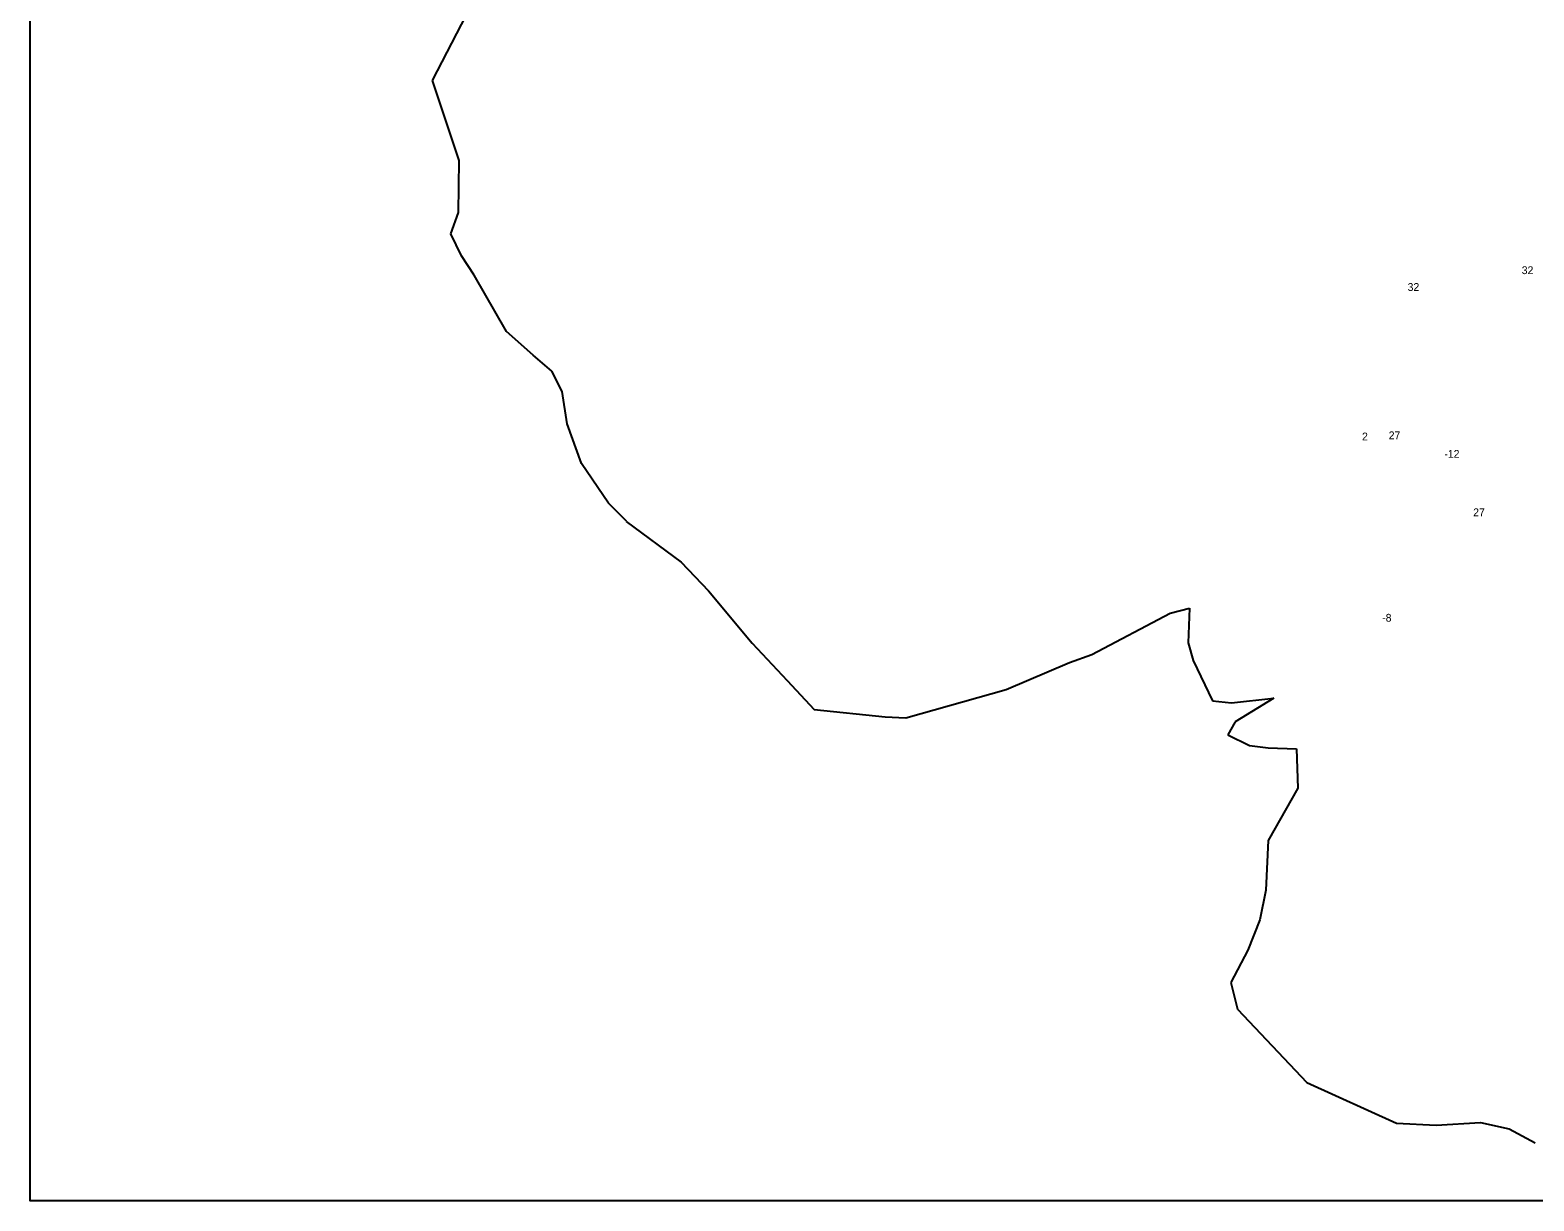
# Model space of a CAD drawing. Extents: x -772884 to -769704, y -986653 to -984166.
# Drawn here: x -772884 to -771287, y -986653 to -985410 of the extents above; entities that cross this region are included whole.
import ezdxf

# ---------------------------------------------------------------- set-up
doc = ezdxf.new("R2010")
doc.units = 0
doc.layers.add('Vrstva 15', color=7, linetype='Continuous')
doc.layers.add('Vrstva 24', color=7, linetype='Continuous')

msp = doc.modelspace()

# ---------------------------------------------------------------- linework, layer by layer
at = {"layer": 'Vrstva 15'}
for p, q in [((-772456.23, -985463.11), (-772400.73, -985355.31)), ((-772427.89, -985548.21), (-772456.23, -985463.11)), ((-772428.63, -985603.28), (-772427.89, -985548.21)), ((-772436.92, -985626), (-772428.63, -985603.28)), ((-772425.4, -985649.39), (-772436.92, -985626)), ((-772412.04, -985669.95), (-772425.4, -985649.39)), ((-772377.83, -985729.71), (-772412.04, -985669.95)), ((-772349.21, -985754.68), (-772377.83, -985729.71)), ((-772329.68, -985771.86), (-772349.21, -985754.68)), ((-772318.52, -985793.3), (-772329.68, -985771.86)), ((-772313.24, -985827.67), (-772318.52, -985793.3)), ((-772298.12, -985869.96), (-772313.24, -985827.67)), ((-772269.49, -985912.11), (-772298.12, -985869.96)), ((-772250.262, -985931.088), (-772269.49, -985912.11)), ((-772250.56, -985931.49), (-772192.24, -985974.75)), ((-772192.24, -985974.75), (-772163.18, -986005.14)), ((-772163.18, -986005.14), (-772116.66, -986060.78)), ((-771673.06, -986028.88), (-771652.46, -986023.5)), ((-771652.46, -986023.5), (-771653.63, -986060.2)), ((-771756.06, -986072.81), (-771673.06, -986028.88)), ((-772116.66, -986060.78), (-772079.67, -986100.27)), ((-771779.84, -986081.04), (-771756.06, -986072.81)), ((-771653.63, -986060.2), (-771648.5, -986079.14)), ((-771847.2, -986109.75), (-771779.84, -986081.04)), ((-771648.5, -986079.14), (-771627.8, -986121.91)), ((-772079.67, -986100.27), (-772050.91, -986131.15)), ((-771953.61, -986140.1), (-771847.2, -986109.75)), ((-771627.8, -986121.91), (-771607.7, -986123.97)), ((-771607.7, -986123.97), (-771562.93, -986119.01)), ((-771562.93, -986119.01), (-771603.88, -986144.12)), ((-772050.91, -986131.15), (-771975.4, -986138.86)), ((-771975.4, -986138.86), (-771953.61, -986140.1)), ((-771603.88, -986144.12), (-771611.51, -986157.92)), ((-771611.51, -986157.92), (-771588.62, -986169.52)), ((-771588.62, -986169.52), (-771568.8, -986171.72)), ((-771568.8, -986171.72), (-771538.71, -986173.04)), ((-771538.71, -986173.04), (-771537.4, -986214.71)), ((-771537.4, -986214.71), (-771569.02, -986270.36)), ((-771569.02, -986270.36), (-771571.45, -986322.99)), ((-771571.45, -986322.99), (-771577.61, -986354.41)), ((-771577.61, -986354.41), (-771590.53, -986386.61)), ((-771590.53, -986386.61), (-771608.59, -986421.15)), ((-771608.59, -986421.15), (-771601.4, -986449.38)), ((-771601.4, -986449.38), (-771527.94, -986527.23)), ((-771527.94, -986527.23), (-771432.42, -986570.64)), ((-771432.42, -986570.64), (-771390.31, -986572.72)), ((-771390.31, -986572.72), (-771343.55, -986569.8)), ((-771343.55, -986569.8), (-771312.95, -986576.54)), ((-771312.95, -986576.54), (-771285.5, -986591.52))]:
    msp.add_line(p, q, dxfattribs=at)
msp.add_lwpolyline([(-772883.58, -984166.02), (-769704.46, -984166.02), (-769704.46, -986653.05), (-772883.58, -986653.05)], close=True, dxfattribs=at)

# ---------------------------------------------------------------- texts
at = {"layer": 'Vrstva 24'}
for s, height, p in [('32', 8.2944, (-771299.573, -985668.725)), ('32', 8.2944, (-771420.763, -985686.575)), ('2', 8.294, (-771469.156, -985845.325)), ('27', 8.2944, (-771440.846, -985844.105)), ('-12', 8.2944, (-771381.722, -985863.755)), ('27', 8.2944, (-771351.126, -985925.855)), ('-8', 8.2944, (-771447.771, -986037.865))]:
    msp.add_text(s, height=height, dxfattribs=at).set_placement(p)

doc.saveas('drawing.dxf')
